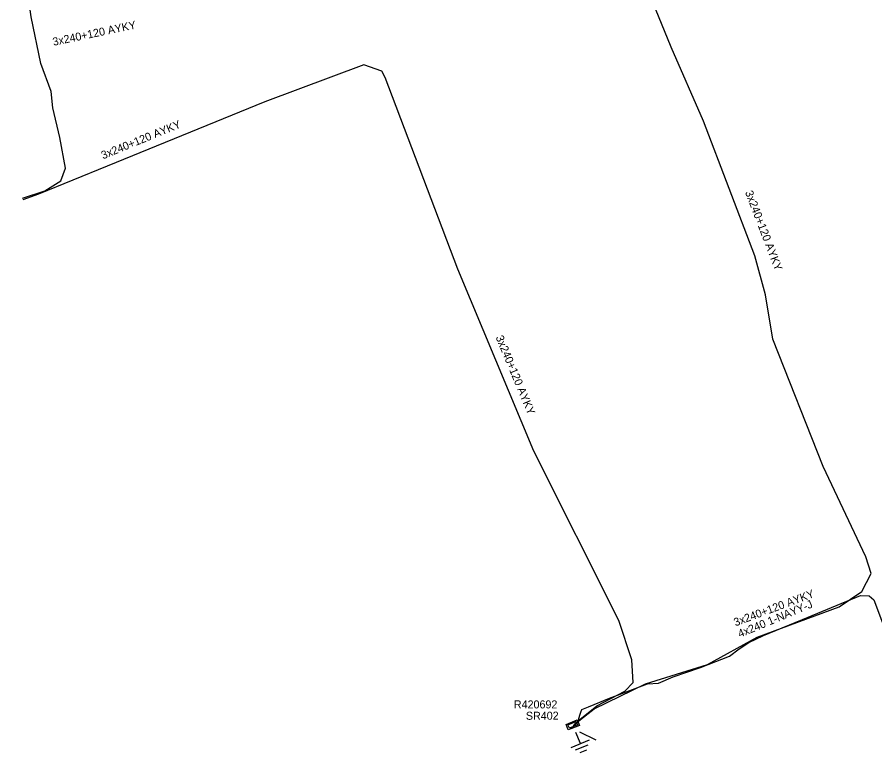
# Model space of a CAD drawing. Extents: x -540028 to -538776, y -1157064 to -1155670.
# Drawn here: x -540002.7 to -539895.6, y -1156132.6 to -1156040.4 of the extents above; entities that cross this region are included whole.
import ezdxf

# ---------------------------------------------------------------- set-up
doc = ezdxf.new("R2010")
doc.units = 0
for name, color, linetype in [('Vrstva 15', 7, 'Continuous'), ('Vrstva 2', 7, 'Continuous'), ('Vrstva 28', 7, 'Continuous'), ('Vrstva 29', 7, 'Continuous'), ('Vrstva 30', 7, 'Continuous'), ('Vrstva 5', 7, 'Continuous'), ('Vrstva 59', 7, 'Continuous'), ('Vrstva 6', 7, 'Continuous')]:
    doc.layers.add(name, color=color, linetype=linetype)

# ---------------------------------------------------------------- blocks, each defined once
blk = doc.blocks.new('132')
at = {"layer": 'Vrstva 2'}
for points in [[(-1.5, 1.5), (1.5, 1.5), (1.5, 0), (-1.5, 0)], [(-1.1, 1.2), (1.1, 1.2), (1.1, 0.3), (-1.1, 0.3)]]:
    blk.add_lwpolyline(points, close=True, dxfattribs=at)
blk = doc.blocks.new('11')
at = {"layer": 'Vrstva 2'}
for p, q in [((0, -4.3), (0, -1.3)), ((-2.5, -4.3), (2.5, -4.3)), ((-1.7, -5.3), (1.7, -5.3)), ((-0.9, -6.3), (0.9, -6.3))]:
    blk.add_line(p, q, dxfattribs=at)

msp = doc.modelspace()

# ---------------------------------------------------------------- linework, layer by layer
at = {"layer": 'Vrstva 5'}
for points in [[(-539933.17, -1156129.17), (-539933.06, -1156128.77), (-539932.34, -1156128.15), (-539930.63, -1156126.85), (-539924.21, -1156123.71), (-539916.47, -1156121.29), (-539910.25, -1156117.9), (-539900.02, -1156114.09), (-539897.19, -1156112.19), (-539896.02, -1156109.93), (-539896.71, -1156107.86), (-539902.02, -1156096.58), (-539908.3, -1156080.67), (-539909.23, -1156075.13), (-539910.55, -1156070.25), (-539916.99, -1156053.43), (-539920.99, -1156044.18), (-539926.8, -1156029.97)], [(-540002, -1156063.03), (-539999.22, -1156062.13), (-539997.22, -1156060.88), (-539996.66, -1156059.27), (-539997.35, -1156055.47), (-539998.23, -1156051.74), (-539998.43, -1156049.71), (-539999.71, -1156046.23), (-540000.93, -1156040.38), (-540001.68, -1156034.96), (-540002.68, -1156032.01)], [(-539933.25, -1156129.2), (-539933.06, -1156128.74), (-539932.38, -1156128.11), (-539930.31, -1156126.47), (-539926.79, -1156124.63), (-539925.77, -1156123.54), (-539925.94, -1156120.73), (-539927.55, -1156115.8), (-539938.16, -1156094.63), (-539947.65, -1156071.89), (-539956.72, -1156047.95), (-539957.16, -1156047.19), (-539959.39, -1156046.37), (-539971.75, -1156050.99), (-539991.43, -1156059.03), (-540000, -1156062.55), (-540001.96, -1156063.23)], [(-539933.37, -1156129.29), (-539933.15, -1156128.89), (-539932.94, -1156128.76), (-539932.64, -1156128.3), (-539932.31, -1156127.25), (-539932.17, -1156126.91), (-539931.35, -1156126.57), (-539928.69, -1156125.5), (-539923.95, -1156123.7), (-539922.58, -1156123.61), (-539920.75, -1156122.85), (-539917.34, -1156121.65), (-539913.71, -1156120.25), (-539912.51, -1156119.34), (-539911.32, -1156118.54), (-539909.5, -1156117.66), (-539903.89, -1156115.39), (-539897.35, -1156112.66), (-539896.27, -1156112.71), (-539895.7, -1156113.23), (-539894.6, -1156116.08)]]:
    msp.add_lwpolyline(points, dxfattribs=at)
at = {"layer": 'Vrstva 59'}
msp.add_lwpolyline([(-539932.45, -1156129.72), (-539930.4, -1156130.69)], dxfattribs=at)

# ---------------------------------------------------------------- block references
at = {"layer": 'Vrstva 15', "xscale": 0.5, "yscale": 0.49999999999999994, "rotation": 22.18378066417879}
msp.add_blockref('11', (-539933.16, -1156129.19), dxfattribs=at)
at = {"layer": 'Vrstva 28', "xscale": 0.5000000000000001, "yscale": 0.5, "rotation": 22.183780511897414}
msp.add_blockref('132', (-539933.16, -1156129.19), dxfattribs=at)

# ---------------------------------------------------------------- texts
at = {"layer": 'Vrstva 29'}
msp.add_text('R420692', height=1, dxfattribs=at).set_placement((-539940.65, -1156126.78))
at = {"layer": 'Vrstva 30'}
msp.add_text('SR402', height=1, rotation=0.184, dxfattribs=at).set_placement((-539939.15, -1156128.2))
at = {"layer": 'Vrstva 6'}
for s, rotation, p in [('3x240+120 AYKY', 11.825, (-539998.14, -1156044.01)), ('3x240+120 AYKY', 22.226, (-539991.95, -1156058.19)), ('3x240+120 AYKY', 290.964, (-539911.8, -1156062.3)), ('3x240+120 AYKY', 292.653, (-539942.95, -1156080.42)), ('3x240+120 AYKY', 20.444, (-539912.98, -1156116.54)), ('4x240 1-NAYY-J', 22.657, (-539912.43, -1156117.96))]:
    msp.add_text(s, height=1, rotation=rotation, dxfattribs=at).set_placement(p)

doc.saveas('drawing.dxf')
